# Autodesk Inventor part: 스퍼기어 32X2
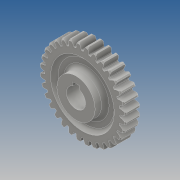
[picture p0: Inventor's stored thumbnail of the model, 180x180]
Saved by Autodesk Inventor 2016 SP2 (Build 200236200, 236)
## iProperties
Created: 2018-07
Part Number: 스퍼기어 32X2
Material: Generic
Document SubType Name: Modeling
Designer: Administrator
Density: 1 g/cm^3
Appearance: Default
Author: Administrator
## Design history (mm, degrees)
sketch "스케치1"
  geometry: L1 (-11, 0)-(11, 0); L2 (-11, 0)-(-11, 7.5); L3 (-11, 15)-(-3, 15); L4 (-3, 15)-(-3, 25); L5 (-3, 25)-(-6, 25); L6 (-6, 25)-(-6, 34); L7 (-6, 34)-(6, 34); L8 (6, 34)-(6, 25); L9 (6, 25)-(3, 25); L10 (3, 25)-(3, 15); L11 (3, 15)-(11, 15); L12 (11, 15)-(11, 7.5); L13 (-11, 7.5)-(11, 7.5); L14 (-11, 7.5)-(-11, 15); L15 (11, 7.5)-(11, 0); 3 further points
  constraints: 30 end point, 10 perpendicular, 4 point on line, 2 horizontal, 2 midpoint, 2 vertical, 1 coincident, 1 collinear, 1 vertical alignment
  dimensions: "d0" = 22 distance of L1.start L1.end; "d1" = 15 distance of L1.start L3.start; "d2" = 12 distance of L6.end L7.end; "d3" = 6 distance between parallel lines of L4 L10; "d4" = 50 diameter of L9 L1; "d5" = 68 diameter of L7 L1; "d6" = 15 diameter of L13 L1
revolve "회전1" sketch "스케치1" stored, may be unused: angle "d7" = 90 deg
sketch "스케치3"
  geometry: L1 (-2.5, 9.8)-(2.5, 9.8); L2 (2.5, 9.8)-(2.5, 7.071); L3 (-2.5, 7.071)-(-2.5, 9.8); A1 r 7.5 centre (0, 0) between (2.5, 7.071) and (-2.5, 7.071) reference
  constraints: 6 end point, 2 parallel, 2 point on circle, 1 horizontal, 1 perpendicular
  dimensions: "d23" = 5 distance of L1.start L1.end; "d24" = 2.3 distance edge to line of A1 L1
extrude "돌출2" cut sketch "스케치3" stored distance "d25" = 12; taper "d26" = 0 deg
sketch "스케치4"
  geometry: L1 (0, 0)-(3.349, 33.835); L2 (2.338, 29.407)-(2.781, 33.886); L3 (1.339, 29.47)-(1.585, 31.961); L4 (0.838, 29.488)-(1.085, 31.982); L5 (0, 0)-(0, 34); A1 r 34 centre (0, 0) between (3.349, 33.835) and (0, 34) reference; A2 r 34 centre (0, 0) between (3.349, 33.835) and (0, 34) reference; A3 r 32 centre (0, 0) between (1.085, 31.982) and (1.585, 31.961); A4 r 9.275 centre (10.004, 28.068) between (2.781, 33.886) and (0.838, 29.488); A5 r 9.275 centre (-10.004, 28.068) between (-0.838, 29.488) and (-2.781, 33.886); A6 r 29.5 centre (0, 0) between (0.838, 29.488) and (-0.838, 29.488); A7 r 34 centre (0, 0) between (2.781, 33.886) and (-2.781, 33.886)
  constraints: 16 point on circle, 10 end point, 5 centre point, 4 coincident, 3 parallel, 3 symmetric about line, 1 vertical, 1 other
  dimensions: "d30" = 64 diameter of A3; "d36" = 1.57 distance between parallel lines of L3 L1; "d37" = 1 distance between parallel lines of L3 L2; "d38" = 0.5 distance between parallel lines of L4 L3; "d39" = 5.652 deg angle of L5 L1
extrude "돌출3" cut sketch "스케치4" stored distance "d40" = 12; taper "d41" = 0 deg
chamfer "모따기4" distance "d55" = 1; stored, may be unused: second distance "d56" = 2, angle "d57" = 45 deg
fillet "모깎기4" dims "d58" = 0.5
fillet "모깎기5" dims "d62" = 3
node "솔리드1"
pattern_circular "원형 패턴4" dims angle "d60" = 360 deg
other parameters: "d27" = 1.57, "d28" = 1, "d29" = 0.5, "d33" = 1.57, "d34" = 1, "d35" = 0.5
